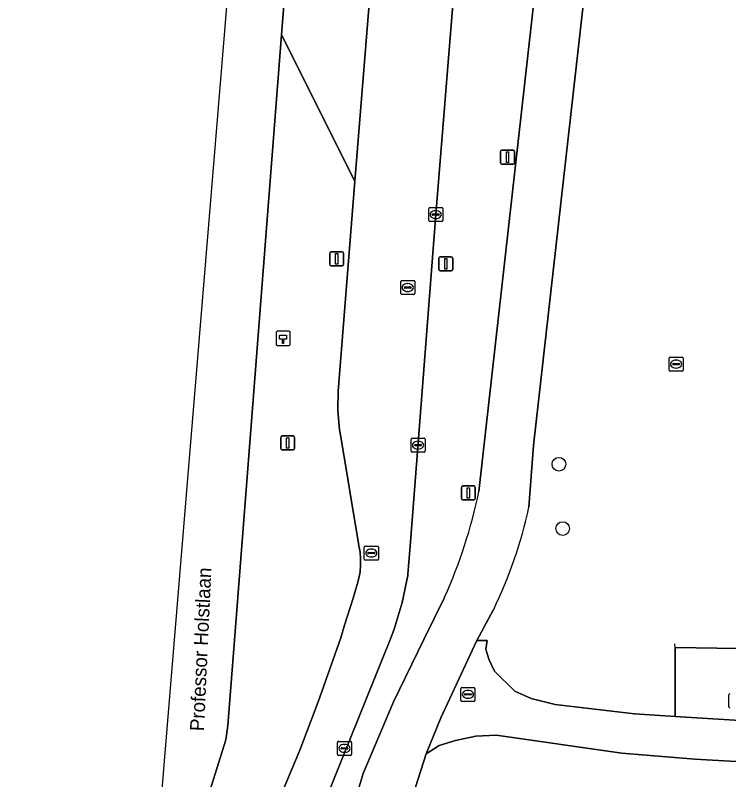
# Model space of a CAD drawing. Extents: x 160203 to 161530, y 379528 to 381797.
# Drawn here: x 160203.2 to 160254.1, y 379665.1 to 379719.6 of the extents above; entities that cross this region are included whole.
import ezdxf

# ---------------------------------------------------------------- set-up
doc = ezdxf.new("R2010")
doc.units = 0
for name, color, linetype in [('IMGEO_Berm_groen', 7, 'Continuous'), ('IMGEO_Boom', 7, 'Continuous'), ('IMGEO_Fietspad_gesloten', 7, 'Continuous'), ('IMGEO_Grasland_overig', 7, 'Continuous'), ('IMGEO_Groenvoorziening', 7, 'Continuous'), ('IMGEO_Hectometerpaal', 7, 'Continuous'), ('IMGEO_Hek', 7, 'Continuous'), ('IMGEO_Kolk', 7, 'Continuous'), ('IMGEO_Lichtmast', 7, 'Continuous'), ('IMGEO_Openbare_ruimte_label', 7, 'Continuous'), ('IMGEO_Rijbaan_regionaal_gesloten', 7, 'Continuous'), ('IMGEO_Rioolput', 7, 'Continuous'), ('IMGEO_Verkeersbordpaal', 7, 'Continuous')]:
    doc.layers.add(name, color=color, linetype=linetype)

msp = doc.modelspace()

# ---------------------------------------------------------------- linework, layer by layer
at = {"layer": 'IMGEO_Berm_groen'}
for points in [[(160242.114, 379737.894), (160242.378, 379740.301), (160235.341, 379731.02), (160234.591, 379722.805), (160234.502, 379721.827), (160233.173, 379705.38), (160231.363, 379681.762), (160231.198, 379679.745), (160231.183, 379679.651), (160230.778, 379677.725), (160230.202, 379675.844), (160229.942, 379675.15), (160220.821, 379652.521), (160220.438, 379650.535), (160225.932, 379650.167), (160226.429, 379657.385), (160227.115, 379661.928), (160227.638, 379664.367), (160227.998, 379665.554), (160230.157, 379670.66), (160232.326, 379675.107), (160233.804, 379678.104)], [(160236.255, 379685.637), (160242.114, 379737.894)], [(160229.008, 379732.704), (160223.36, 379733.154), (160222.629, 379723.881), (160222.18, 379718.179), (160227.415, 379707.754), (160228.665, 379723.336)], [(160219.468, 379657.633), (160223.488, 379667.218), (160224.801, 379670.649), (160226.403, 379675.215), (160226.677, 379676.114), (160227.303, 379678.04), (160227.576, 379679.014), (160227.7, 379679.465), (160227.783, 379679.925), (160227.825, 379680.391), (160227.825, 379680.858), (160227.783, 379681.324), (160227.7, 379681.784), (160227.663, 379681.937), (160226.36, 379689.817), (160226.329, 379690.043), (160226.21, 379691.422), (160226.215, 379692.806), (160227.415, 379707.754), (160222.18, 379718.179), (160218.869, 379675.352), (160218.366, 379668.969), (160218.224, 379667.943), (160214.934, 379657.505)]]:
    msp.add_lwpolyline(points, dxfattribs=at)
msp.add_arc((160199.552, 379693.414), 37.517, 335.9165, 348.037, dxfattribs=at)
at = {"layer": 'IMGEO_Boom'}
for centre in [(160241.957, 379687.59), (160242.22, 379683.007)]:
    msp.add_circle(centre, 0.489, dxfattribs=at)
at = {"layer": 'IMGEO_Fietspad_gesloten'}
for points in [[(160239.818, 379684.538), (160240.149, 379688.922), (160245.625, 379737.588), (160246.976, 379750), (160247.434, 379754.207), (160247.768, 379757.276), (160251.013, 379784.598)], [(160242.114, 379737.894), (160236.255, 379685.637)], [(160233.804, 379678.104), (160232.326, 379675.107), (160230.157, 379670.66), (160227.998, 379665.554), (160227.638, 379664.367)], [(160230.775, 379661.61), (160232.495, 379666.954), (160233.537, 379669.518), (160236.103, 379675.038), (160237.279, 379677.201)]]:
    msp.add_lwpolyline(points, dxfattribs=at)
for centre, radius, start, end in [((160199.552, 379693.414), 37.517, 335.9165, 348.037), ((160207.983, 379691.447), 32.577, 334.0677, 347.7555)]:
    msp.add_arc(centre, radius, start, end, dxfattribs=at)
at = {"layer": 'IMGEO_Grasland_overig'}
for points in [[(160251.013, 379784.598), (160247.768, 379757.276), (160247.434, 379754.207), (160246.976, 379750), (160245.625, 379737.588), (160240.149, 379688.922), (160239.818, 379684.538)], [(160237.279, 379677.201), (160236.103, 379675.038), (160236.841, 379675.025), (160236.754, 379674.399), (160236.96, 379673.703), (160237.368, 379672.848), (160238.818, 379671.425), (160239.981, 379670.898), (160241.681, 379670.475), (160247.336, 379669.791), (160250.231, 379669.61), (160250.231, 379674.539), (160257.676, 379674.411), (160264.021, 379674.552), (160265.196, 379674.843), (160275.591, 379675.062), (160289.301, 379675.175), (160297.441, 379675.353), (160306.402, 379675.379), (160325.257, 379675.801)], [(160261.753, 379668.892), (160250.231, 379669.61), (160247.336, 379669.791), (160241.681, 379670.475), (160239.981, 379670.898), (160238.818, 379671.425), (160237.368, 379672.848), (160236.96, 379673.703), (160236.754, 379674.399), (160236.841, 379675.025), (160236.103, 379675.038), (160233.537, 379669.518), (160232.495, 379666.954), (160233.427, 379667.542), (160234.581, 379667.912), (160236.035, 379668.205), (160237.492, 379668.279), (160246.445, 379667.009), (160251.637, 379666.58), (160263.798, 379665.879)]]:
    msp.add_lwpolyline(points, dxfattribs=at)
msp.add_arc((160207.983, 379691.447), 32.577, 334.0677, 347.7555, dxfattribs=at)
at = {"layer": 'IMGEO_Groenvoorziening'}
for points in [[(160325.257, 379675.801), (160306.402, 379675.379), (160297.441, 379675.353), (160289.301, 379675.175), (160275.591, 379675.062), (160265.196, 379674.843), (160264.021, 379674.552), (160257.676, 379674.411), (160250.231, 379674.539), (160250.231, 379669.61), (160261.753, 379668.892), (160272.733, 379668.499), (160282.774, 379668.297), (160289.58, 379668.203), (160316.379, 379668.581), (160343.92, 379668.527)], [(160328.462, 379665.484), (160317.066, 379665.574), (160289.607, 379665.409), (160263.798, 379665.879), (160251.637, 379666.58), (160246.445, 379667.009), (160237.492, 379668.279), (160236.035, 379668.205), (160234.581, 379667.912), (160233.427, 379667.542), (160232.495, 379666.954), (160230.775, 379661.61)]]:
    msp.add_lwpolyline(points, dxfattribs=at)
at = {"layer": 'IMGEO_Hectometerpaal'}
for p, q in [((160221.803, 379696.977), (160221.803, 379696.136)), ((160221.803, 379696.977), (160221.803, 379696.136)), ((160222.719, 379697.061), (160221.878, 379697.061)), ((160222.719, 379697.061), (160221.878, 379697.061)), ((160222.803, 379696.145), (160222.803, 379696.986)), ((160222.803, 379696.145), (160222.803, 379696.986)), ((160221.887, 379696.061), (160222.728, 379696.061)), ((160221.887, 379696.061), (160222.728, 379696.061))]:
    msp.add_line(p, q, dxfattribs=at)
msp.add_lwpolyline([(160222.328, 379696.205), (160222.268, 379696.205), (160222.268, 379696.51), (160222.048, 379696.51), (160222.048, 379696.779), (160222.548, 379696.779), (160222.548, 379696.51), (160222.328, 379696.51), (160222.328, 379696.205)], dxfattribs=at)
for centre, start, end in [((160221.881, 379696.983), 92.4484, 184.2845), ((160221.881, 379696.983), 92.4484, 184.2845), ((160222.725, 379696.983), 2.4484, 94.2845), ((160222.725, 379696.983), 2.4484, 94.2845), ((160221.881, 379696.139), 182.4484, 274.2845), ((160221.881, 379696.139), 182.4484, 274.2845), ((160222.725, 379696.139), 272.4484, 4.2845), ((160222.725, 379696.139), 272.4484, 4.2845)]:
    msp.add_arc(centre, 0.0779, start, end, dxfattribs=at)
at = {"layer": 'IMGEO_Hek'}
for points in [[(160450.091, 379677.562), (160424.448, 379677.335), (160383.862, 379676.665), (160376.44, 379676.473), (160363.649, 379676.31), (160355.826, 379676.315), (160342.079, 379675.983), (160325.257, 379675.801), (160306.402, 379675.379), (160297.441, 379675.353), (160289.301, 379675.175), (160275.591, 379675.062), (160265.196, 379674.843), (160264.021, 379674.552), (160257.676, 379674.411), (160250.231, 379674.539)], [(160250.231, 379674.539), (160250.222, 379674.781)]]:
    msp.add_lwpolyline(points, dxfattribs=at)
at = {"layer": 'IMGEO_Kolk'}
for p, q in [((160232.748, 379705.88), (160233.6, 379705.88)), ((160232.673, 379704.954), (160232.673, 379705.806)), ((160232.932, 379705.374), (160232.932, 379705.386)), ((160233.37, 379705.337), (160232.972, 379705.337)), ((160232.975, 379705.423), (160233.373, 379705.423)), ((160233.161, 379705.66), (160233.186, 379705.66)), ((160233.416, 379705.386), (160233.416, 379705.374)), ((160233.674, 379705.806), (160233.674, 379704.954)), ((160233.6, 379704.88), (160232.748, 379704.88)), ((160233.184, 379705.1), (160233.159, 379705.1)), ((160231.414, 379688.522), (160231.414, 379689.374)), ((160231.489, 379689.448), (160232.341, 379689.448)), ((160231.716, 379688.991), (160232.114, 379688.991)), ((160231.902, 379689.228), (160231.927, 379689.228)), ((160232.415, 379689.374), (160232.415, 379688.522)), ((160232.341, 379688.448), (160231.489, 379688.448)), ((160231.673, 379688.942), (160231.673, 379688.954)), ((160232.111, 379688.905), (160231.713, 379688.905)), ((160231.925, 379688.668), (160231.9, 379688.668)), ((160232.157, 379688.954), (160232.157, 379688.942)), ((160234.969, 379670.762), (160234.969, 379671.614)), ((160235.044, 379671.688), (160235.896, 379671.688)), ((160235.97, 379671.614), (160235.97, 379670.762)), ((160235.228, 379671.182), (160235.228, 379671.194)), ((160235.666, 379671.145), (160235.268, 379671.145)), ((160235.271, 379671.231), (160235.669, 379671.231)), ((160235.457, 379671.468), (160235.482, 379671.468)), ((160235.712, 379671.194), (160235.712, 379671.182)), ((160235.896, 379670.688), (160235.044, 379670.688)), ((160235.48, 379670.908), (160235.455, 379670.908)), ((160226.174, 379666.916), (160226.174, 379667.768)), ((160226.249, 379667.842), (160227.101, 379667.842)), ((160227.175, 379667.768), (160227.175, 379666.916)), ((160226.433, 379667.336), (160226.433, 379667.348)), ((160226.871, 379667.299), (160226.473, 379667.299)), ((160226.476, 379667.385), (160226.874, 379667.385)), ((160226.662, 379667.622), (160226.687, 379667.622)), ((160226.917, 379667.348), (160226.917, 379667.336)), ((160227.101, 379666.842), (160226.249, 379666.842)), ((160226.685, 379667.062), (160226.66, 379667.062))]:
    msp.add_line(p, q, dxfattribs=at)
for points in [[(160232.748, 379705.88), (160233.6, 379705.88)], [(160232.673, 379704.954), (160232.673, 379705.806)], [(160233.674, 379705.806), (160233.674, 379704.954)], [(160233.6, 379704.88), (160232.748, 379704.88)], [(160231.414, 379688.522), (160231.414, 379689.374)], [(160231.489, 379689.448), (160232.341, 379689.448)], [(160232.415, 379689.374), (160232.415, 379688.522)], [(160232.341, 379688.448), (160231.489, 379688.448)], [(160234.969, 379670.762), (160234.969, 379671.614)], [(160235.044, 379671.688), (160235.896, 379671.688)], [(160235.97, 379671.614), (160235.97, 379670.762)], [(160235.896, 379670.688), (160235.044, 379670.688)], [(160226.174, 379666.916), (160226.174, 379667.768)], [(160226.249, 379667.842), (160227.101, 379667.842)], [(160227.175, 379667.768), (160227.175, 379666.916)], [(160227.101, 379666.842), (160226.249, 379666.842)]]:
    msp.add_lwpolyline(points, dxfattribs=at)
for centre, radius, start, end in [((160232.75, 379705.804), 0.0765, 91.552, 178.448), ((160232.75, 379705.804), 0.0765, 91.552, 178.448), ((160233.598, 379705.804), 0.0765, 1.552, 88.448), ((160233.598, 379705.804), 0.0765, 1.552, 88.448), ((160232.972, 379705.383), 0.0403, 85.8775, 175.7526), ((160232.969, 379705.373), 0.0366, 178.938, 274.7102), ((160233.373, 379705.38), 0.043, 264.8664, 352.4533), ((160233.377, 379705.385), 0.0386, 1.7309, 96.639), ((160232.75, 379704.956), 0.0765, 181.552, 268.448), ((160232.75, 379704.956), 0.0765, 181.552, 268.448), ((160233.598, 379704.956), 0.0765, 271.552, 358.448), ((160233.598, 379704.956), 0.0765, 271.552, 358.448), ((160231.491, 379689.372), 0.0765, 91.552, 178.448), ((160231.491, 379689.372), 0.0765, 91.552, 178.448), ((160231.713, 379688.951), 0.0403, 85.8775, 175.7526), ((160232.118, 379688.953), 0.0386, 1.7309, 96.639), ((160232.339, 379689.372), 0.0765, 1.552, 88.448), ((160232.339, 379689.372), 0.0765, 1.552, 88.448), ((160231.491, 379688.524), 0.0765, 181.552, 268.448), ((160231.491, 379688.524), 0.0765, 181.552, 268.448), ((160231.71, 379688.941), 0.0366, 178.938, 274.7102), ((160232.114, 379688.948), 0.043, 264.8664, 352.4533), ((160232.339, 379688.524), 0.0765, 271.552, 358.448), ((160232.339, 379688.524), 0.0765, 271.552, 358.448), ((160235.046, 379671.612), 0.0765, 91.552, 178.448), ((160235.046, 379671.612), 0.0765, 91.552, 178.448), ((160235.894, 379671.612), 0.0765, 1.552, 88.448), ((160235.894, 379671.612), 0.0765, 1.552, 88.448), ((160235.268, 379671.191), 0.0403, 85.8775, 175.7526), ((160235.265, 379671.181), 0.0366, 178.938, 274.7102), ((160235.669, 379671.188), 0.043, 264.8664, 352.4533), ((160235.673, 379671.193), 0.0386, 1.7309, 96.639), ((160235.046, 379670.764), 0.0765, 181.552, 268.448), ((160235.046, 379670.764), 0.0765, 181.552, 268.448), ((160235.894, 379670.764), 0.0765, 271.552, 358.448), ((160235.894, 379670.764), 0.0765, 271.552, 358.448), ((160226.251, 379667.766), 0.0765, 91.552, 178.448), ((160226.251, 379667.766), 0.0765, 91.552, 178.448), ((160227.099, 379667.766), 0.0765, 1.552, 88.448), ((160227.099, 379667.766), 0.0765, 1.552, 88.448), ((160226.473, 379667.345), 0.0403, 85.8775, 175.7526), ((160226.47, 379667.335), 0.0366, 178.938, 274.7102), ((160226.874, 379667.342), 0.043, 264.8664, 352.4533), ((160226.878, 379667.347), 0.0386, 1.7309, 96.639), ((160226.251, 379666.918), 0.0765, 181.552, 268.448), ((160226.251, 379666.918), 0.0765, 181.552, 268.448), ((160227.099, 379666.918), 0.0765, 271.552, 358.448), ((160227.099, 379666.918), 0.0765, 271.552, 358.448)]:
    msp.add_arc(centre, radius, start, end, dxfattribs=at)
for centre, major_axis, ratio, start_param, end_param in [((160233.16, 379705.38), (-0.387, 0.002), 0.722429, 4.712389, 7.853982), ((160233.185, 379705.38), (-0.39, 0.002), 0.717154, 1.570796, 4.712389), ((160231.901, 379688.948), (-0.387, 0.002), 0.722429, 4.712389, 7.853982), ((160231.926, 379688.948), (-0.39, 0.002), 0.717154, 1.570796, 4.712389), ((160235.456, 379671.188), (-0.387, 0.002), 0.722429, 4.712389, 7.853982), ((160235.481, 379671.188), (-0.39, 0.002), 0.717154, 1.570796, 4.712389), ((160226.661, 379667.342), (-0.387, 0.002), 0.722429, 4.712389, 7.853982), ((160226.686, 379667.342), (-0.39, 0.002), 0.717154, 1.570796, 4.712389)]:
    msp.add_ellipse(centre, major_axis=major_axis, ratio=ratio, start_param=start_param, end_param=end_param, dxfattribs=at)
at = {"layer": 'IMGEO_Lichtmast'}
for p, q in [((160237.792, 379709.076), (160237.792, 379709.876)), ((160237.792, 379709.876), (160237.792, 379709.076)), ((160237.892, 379709.976), (160238.682, 379709.976)), ((160238.682, 379709.976), (160237.892, 379709.976)), ((160238.782, 379709.876), (160238.782, 379709.076)), ((160238.782, 379709.076), (160238.782, 379709.876)), ((160238.682, 379708.976), (160237.892, 379708.976)), ((160237.892, 379708.976), (160238.682, 379708.976)), ((160222.228, 379689.605), (160223.018, 379689.605)), ((160223.018, 379689.605), (160222.228, 379689.605)), ((160222.128, 379688.705), (160222.128, 379689.505)), ((160222.128, 379689.505), (160222.128, 379688.705)), ((160223.118, 379689.505), (160223.118, 379688.705)), ((160223.118, 379688.705), (160223.118, 379689.505)), ((160223.018, 379688.605), (160222.228, 379688.605)), ((160222.228, 379688.605), (160223.018, 379688.605)), ((160235.004, 379685.141), (160235.004, 379685.941)), ((160235.004, 379685.941), (160235.004, 379685.141)), ((160235.104, 379686.041), (160235.894, 379686.041)), ((160235.894, 379686.041), (160235.104, 379686.041)), ((160235.994, 379685.941), (160235.994, 379685.141)), ((160235.994, 379685.141), (160235.994, 379685.941)), ((160235.894, 379685.041), (160235.104, 379685.041)), ((160235.104, 379685.041), (160235.894, 379685.041))]:
    msp.add_line(p, q, dxfattribs=at)
for points in [[(160238.212, 379709.851), (160238.362, 379709.851), (160238.362, 379709.101), (160238.212, 379709.101), (160238.212, 379709.851)], [(160222.548, 379689.48), (160222.698, 379689.48), (160222.698, 379688.73), (160222.548, 379688.73), (160222.548, 379689.48)], [(160235.424, 379685.916), (160235.574, 379685.916), (160235.574, 379685.166), (160235.424, 379685.166), (160235.424, 379685.916)]]:
    msp.add_lwpolyline(points, dxfattribs=at)
for centre, start, end in [((160237.892, 379709.876), 90, 180), ((160237.892, 379709.876), 90, 180), ((160238.682, 379709.876), 0, 90), ((160238.682, 379709.876), 360, 90), ((160237.892, 379709.076), 180, 270), ((160237.892, 379709.076), 180, 270), ((160238.682, 379709.076), 270, 0), ((160238.682, 379709.076), 270, 0), ((160222.228, 379689.505), 90, 180), ((160222.228, 379689.505), 90, 180), ((160223.018, 379689.505), 0, 90), ((160223.018, 379689.505), 360, 90), ((160222.228, 379688.705), 180, 270), ((160222.228, 379688.705), 180, 270), ((160223.018, 379688.705), 270, 0), ((160223.018, 379688.705), 270, 0), ((160235.104, 379685.941), 90, 180), ((160235.104, 379685.941), 90, 180), ((160235.894, 379685.941), 0, 90), ((160235.894, 379685.941), 360, 90), ((160235.104, 379685.141), 180, 270), ((160235.104, 379685.141), 180, 270), ((160235.894, 379685.141), 270, 0), ((160235.894, 379685.141), 270, 0)]:
    msp.add_arc(centre, 0.1, start, end, dxfattribs=at)
at = {"layer": 'IMGEO_Rijbaan_regionaal_gesloten'}
for points in [[(160214.934, 379657.505), (160218.224, 379667.943), (160218.366, 379668.969), (160218.869, 379675.352), (160222.18, 379718.179), (160222.629, 379723.881), (160218.61, 379724.25), (160203.216, 379537.907)], [(160228.665, 379723.336), (160227.415, 379707.754), (160226.215, 379692.806), (160226.21, 379691.422), (160226.329, 379690.043), (160226.36, 379689.817), (160227.663, 379681.937), (160227.7, 379681.784), (160227.783, 379681.324), (160227.825, 379680.858), (160227.825, 379680.391), (160227.783, 379679.925), (160227.7, 379679.465), (160227.576, 379679.014), (160227.303, 379678.04), (160226.677, 379676.114), (160226.403, 379675.215), (160224.801, 379670.649), (160223.488, 379667.218), (160219.468, 379657.633)], [(160220.821, 379652.521), (160229.942, 379675.15), (160230.202, 379675.844), (160230.778, 379677.725), (160231.183, 379679.651), (160231.198, 379679.745), (160231.363, 379681.762), (160233.173, 379705.38), (160234.502, 379721.827)]]:
    msp.add_lwpolyline(points, dxfattribs=at)
at = {"layer": 'IMGEO_Rioolput'}
for p, q in [((160230.68, 379699.754), (160230.68, 379700.606)), ((160230.755, 379700.68), (160231.607, 379700.68)), ((160231.168, 379700.46), (160231.193, 379700.46)), ((160231.681, 379700.606), (160231.681, 379699.754)), ((160230.939, 379700.174), (160230.939, 379700.186)), ((160231.377, 379700.137), (160230.979, 379700.137)), ((160230.982, 379700.223), (160231.38, 379700.223)), ((160231.191, 379699.9), (160231.166, 379699.9)), ((160231.423, 379700.186), (160231.423, 379700.174)), ((160231.607, 379699.68), (160230.755, 379699.68)), ((160249.803, 379694.301), (160249.803, 379695.153)), ((160249.878, 379695.227), (160250.73, 379695.227)), ((160250.291, 379695.007), (160250.316, 379695.007)), ((160250.804, 379695.153), (160250.804, 379694.301)), ((160250.062, 379694.721), (160250.062, 379694.733)), ((160250.5, 379694.684), (160250.102, 379694.684)), ((160250.105, 379694.77), (160250.503, 379694.77)), ((160250.314, 379694.447), (160250.289, 379694.447)), ((160250.546, 379694.733), (160250.546, 379694.721)), ((160250.73, 379694.227), (160249.878, 379694.227)), ((160228.087, 379680.834), (160228.087, 379681.686)), ((160228.162, 379681.76), (160229.014, 379681.76)), ((160228.575, 379681.54), (160228.6, 379681.54)), ((160229.088, 379681.686), (160229.088, 379680.834)), ((160228.346, 379681.254), (160228.346, 379681.266)), ((160228.784, 379681.217), (160228.386, 379681.217)), ((160228.389, 379681.303), (160228.787, 379681.303)), ((160228.598, 379680.98), (160228.573, 379680.98)), ((160228.83, 379681.266), (160228.83, 379681.254)), ((160229.014, 379680.76), (160228.162, 379680.76)), ((160254.051, 379670.303), (160254.051, 379671.155))]:
    msp.add_line(p, q, dxfattribs=at)
for points in [[(160230.68, 379699.754), (160230.68, 379700.606)], [(160230.755, 379700.68), (160231.607, 379700.68)], [(160231.681, 379700.606), (160231.681, 379699.754)], [(160231.607, 379699.68), (160230.755, 379699.68)], [(160249.803, 379694.301), (160249.803, 379695.153)], [(160249.878, 379695.227), (160250.73, 379695.227)], [(160250.804, 379695.153), (160250.804, 379694.301)], [(160250.73, 379694.227), (160249.878, 379694.227)], [(160228.087, 379680.834), (160228.087, 379681.686)], [(160228.162, 379681.76), (160229.014, 379681.76)], [(160229.088, 379681.686), (160229.088, 379680.834)], [(160229.014, 379680.76), (160228.162, 379680.76)], [(160254.051, 379670.303), (160254.051, 379671.155)]]:
    msp.add_lwpolyline(points, dxfattribs=at)
for centre, radius, start, end in [((160230.757, 379700.604), 0.0765, 91.552, 178.448), ((160230.757, 379700.604), 0.0765, 91.552, 178.448), ((160231.605, 379700.604), 0.0765, 1.552, 88.448), ((160231.605, 379700.604), 0.0765, 1.552, 88.448), ((160230.979, 379700.183), 0.0403, 85.8775, 175.7526), ((160230.976, 379700.173), 0.0366, 178.938, 274.7102), ((160231.38, 379700.18), 0.043, 264.8664, 352.4533), ((160231.384, 379700.185), 0.0386, 1.7309, 96.639), ((160230.757, 379699.756), 0.0765, 181.552, 268.448), ((160230.757, 379699.756), 0.0765, 181.552, 268.448), ((160231.605, 379699.756), 0.0765, 271.552, 358.448), ((160231.605, 379699.756), 0.0765, 271.552, 358.448), ((160249.88, 379695.151), 0.0765, 91.552, 178.448), ((160249.88, 379695.151), 0.0765, 91.552, 178.448), ((160250.728, 379695.151), 0.0765, 1.552, 88.448), ((160250.728, 379695.151), 0.0765, 1.552, 88.448), ((160250.102, 379694.73), 0.0403, 85.8775, 175.7526), ((160250.099, 379694.72), 0.0366, 178.938, 274.7102), ((160250.503, 379694.727), 0.043, 264.8664, 352.4533), ((160250.507, 379694.732), 0.0386, 1.7309, 96.639), ((160249.88, 379694.303), 0.0765, 181.552, 268.448), ((160249.88, 379694.303), 0.0765, 181.552, 268.448), ((160250.728, 379694.303), 0.0765, 271.552, 358.448), ((160250.728, 379694.303), 0.0765, 271.552, 358.448), ((160228.164, 379681.684), 0.0765, 91.552, 178.448), ((160228.164, 379681.684), 0.0765, 91.552, 178.448), ((160229.012, 379681.684), 0.0765, 1.552, 88.448), ((160229.012, 379681.684), 0.0765, 1.552, 88.448), ((160228.164, 379680.836), 0.0765, 181.552, 268.448), ((160228.164, 379680.836), 0.0765, 181.552, 268.448), ((160228.386, 379681.263), 0.0403, 85.8775, 175.7526), ((160228.383, 379681.253), 0.0366, 178.938, 274.7102), ((160228.787, 379681.26), 0.043, 264.8664, 352.4533), ((160228.791, 379681.265), 0.0386, 1.7309, 96.639), ((160229.012, 379680.836), 0.0765, 271.552, 358.448), ((160229.012, 379680.836), 0.0765, 271.552, 358.448), ((160254.128, 379671.153), 0.0765, 91.552, 178.448), ((160254.128, 379671.153), 0.0765, 91.552, 178.448), ((160254.128, 379670.305), 0.0765, 181.552, 268.448), ((160254.128, 379670.305), 0.0765, 181.552, 268.448)]:
    msp.add_arc(centre, radius, start, end, dxfattribs=at)
for centre, major_axis, ratio, start_param, end_param in [((160231.167, 379700.18), (-0.387, 0.002), 0.722429, 4.712389, 7.853982), ((160231.192, 379700.18), (-0.39, 0.002), 0.717154, 1.570796, 4.712389), ((160250.29, 379694.727), (-0.387, 0.002), 0.722429, 4.712389, 7.853982), ((160250.315, 379694.727), (-0.39, 0.002), 0.717154, 1.570796, 4.712389), ((160228.574, 379681.26), (-0.387, 0.002), 0.722429, 4.712389, 7.853982), ((160228.599, 379681.26), (-0.39, 0.002), 0.717154, 1.570796, 4.712389)]:
    msp.add_ellipse(centre, major_axis=major_axis, ratio=ratio, start_param=start_param, end_param=end_param, dxfattribs=at)
at = {"layer": 'IMGEO_Verkeersbordpaal'}
for p, q in [((160225.621, 379701.825), (160225.621, 379702.625)), ((160225.621, 379702.625), (160225.621, 379701.825)), ((160225.721, 379702.725), (160226.511, 379702.725)), ((160226.511, 379702.725), (160225.721, 379702.725)), ((160226.611, 379702.625), (160226.611, 379701.825)), ((160226.611, 379701.825), (160226.611, 379702.625)), ((160233.392, 379701.476), (160233.392, 379702.276)), ((160233.392, 379702.276), (160233.392, 379701.476)), ((160233.492, 379702.376), (160234.282, 379702.376)), ((160234.282, 379702.376), (160233.492, 379702.376)), ((160234.382, 379702.276), (160234.382, 379701.476)), ((160234.382, 379701.476), (160234.382, 379702.276)), ((160226.511, 379701.725), (160225.721, 379701.725)), ((160225.721, 379701.725), (160226.511, 379701.725)), ((160234.282, 379701.376), (160233.492, 379701.376)), ((160233.492, 379701.376), (160234.282, 379701.376))]:
    msp.add_line(p, q, dxfattribs=at)
for points in [[(160226.041, 379702.6), (160226.191, 379702.6), (160226.191, 379701.85), (160226.041, 379701.85), (160226.041, 379702.6)], [(160233.812, 379702.251), (160233.962, 379702.251), (160233.962, 379701.501), (160233.812, 379701.501), (160233.812, 379702.251)]]:
    msp.add_lwpolyline(points, dxfattribs=at)
for centre, start, end in [((160225.721, 379702.625), 90, 180), ((160225.721, 379702.625), 90, 180), ((160226.511, 379702.625), 0, 90), ((160226.511, 379702.625), 360, 90), ((160233.492, 379702.276), 90, 180), ((160233.492, 379702.276), 90, 180), ((160234.282, 379702.276), 0, 90), ((160234.282, 379702.276), 360, 90), ((160225.721, 379701.825), 180, 270), ((160225.721, 379701.825), 180, 270), ((160226.511, 379701.825), 270, 0), ((160226.511, 379701.825), 270, 0), ((160233.492, 379701.476), 180, 270), ((160233.492, 379701.476), 180, 270), ((160234.282, 379701.476), 270, 0), ((160234.282, 379701.476), 270, 0)]:
    msp.add_arc(centre, 0.1, start, end, dxfattribs=at)

# ---------------------------------------------------------------- texts
at = {"layer": 'IMGEO_Openbare_ruimte_label'}
msp.add_text('Professor Holstlaan', height=1, rotation=87.3636, dxfattribs=at).set_placement((160216.657, 379668.55))

doc.saveas('drawing.dxf')
